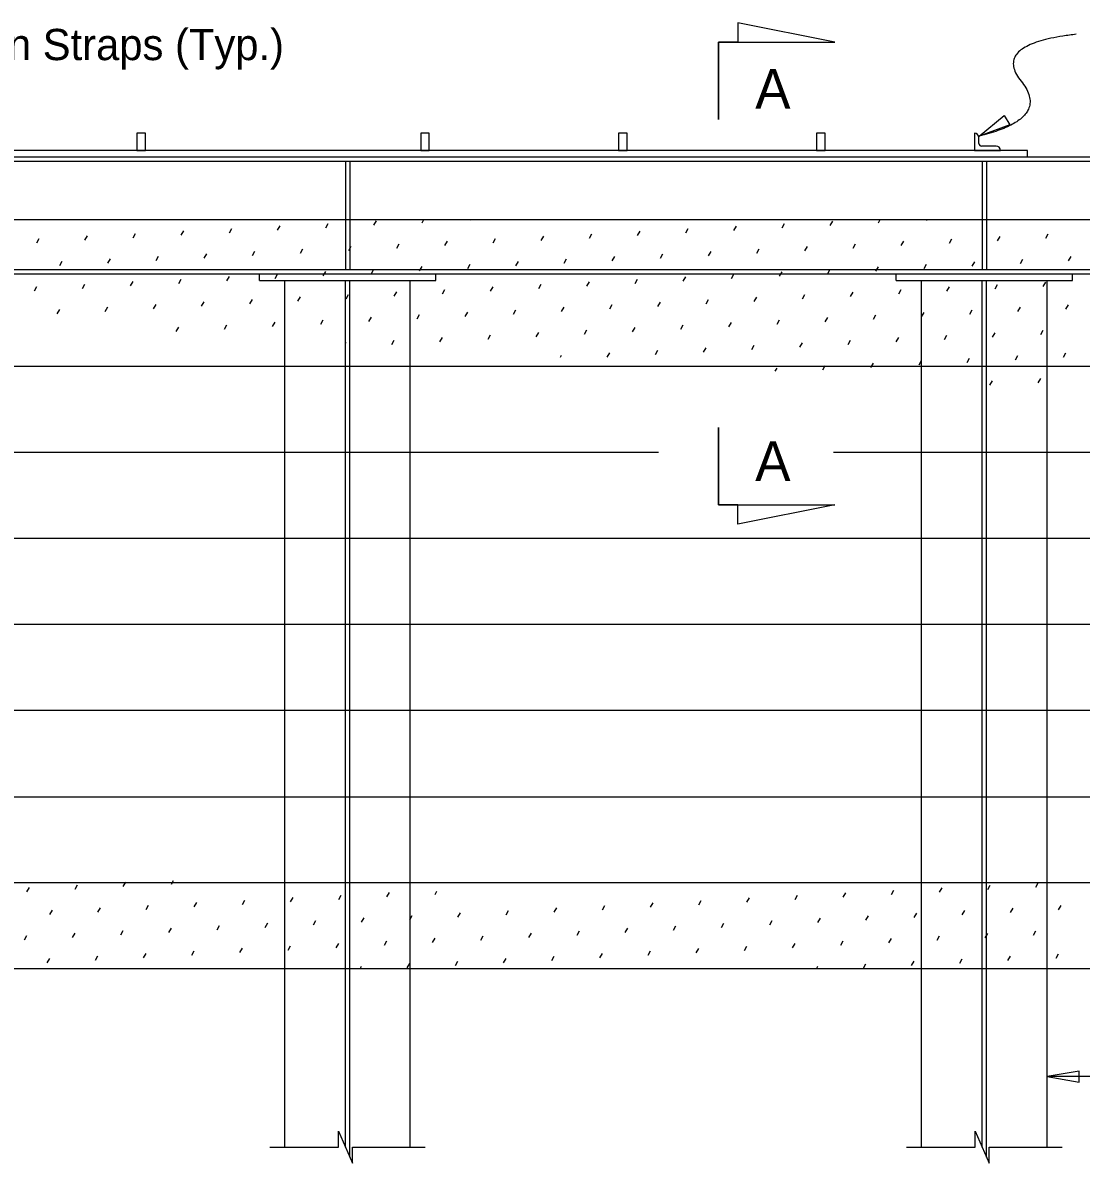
# Model space of a CAD drawing. Extents: x 10624 to 10731, y 76457 to 76509.
# Drawn here: x 10653.36 to 10663.61, y 76483.76 to 76494.8 of the extents above; entities that cross this region are included whole.
import ezdxf

# ---------------------------------------------------------------- set-up
doc = ezdxf.new("R2010")
doc.units = 0
for name, color, linetype in [('Dimension', 7, 'Continuous'), ('GroundLines', 7, 'Continuous'), ('SteelMisc', 7, 'Continuous'), ('SteelMisc_h', 7, 'Continuous'), ('Symbols', 7, 'Continuous'), ('TextStructures', 7, 'Continuous'), ('Wood', 7, 'Continuous'), ('Wood_h', 7, 'Continuous')]:
    doc.layers.add(name, color=color, linetype=linetype)

msp = doc.modelspace()

# ---------------------------------------------------------------- linework, layer by layer
at = {"layer": 'Dimension'}
for p, q in [((10655.831, 76492.793), (10655.855, 76492.835)), ((10656.298, 76492.818), (10656.322, 76492.86)), ((10656.764, 76492.842), (10656.788, 76492.884)), ((10657.23, 76492.866), (10657.248, 76492.897)), ((10657.697, 76492.891), (10657.701, 76492.897)), ((10660.25, 76492.792), (10660.274, 76492.834)), ((10660.717, 76492.816), (10660.741, 76492.858)), ((10661.183, 76492.84), (10661.207, 76492.882)), ((10661.649, 76492.865), (10661.668, 76492.897)), ((10662.116, 76492.889), (10662.121, 76492.897)), ((10653.499, 76492.672), (10653.523, 76492.714)), ((10653.965, 76492.696), (10653.99, 76492.738)), ((10654.432, 76492.72), (10654.456, 76492.762)), ((10654.898, 76492.745), (10654.922, 76492.787)), ((10655.365, 76492.769), (10655.389, 76492.811)), ((10657.918, 76492.67), (10657.942, 76492.712)), ((10658.384, 76492.694), (10658.409, 76492.736)), ((10658.851, 76492.718), (10658.875, 76492.76)), ((10659.317, 76492.743), (10659.341, 76492.785)), ((10659.784, 76492.767), (10659.808, 76492.809)), ((10662.337, 76492.668), (10662.361, 76492.71)), ((10662.803, 76492.692), (10662.828, 76492.734)), ((10663.27, 76492.717), (10663.294, 76492.759)), ((10656.052, 76492.572), (10656.076, 76492.614)), ((10656.519, 76492.597), (10656.543, 76492.639)), ((10656.985, 76492.621), (10657.009, 76492.663)), ((10657.451, 76492.645), (10657.476, 76492.687)), ((10660.471, 76492.571), (10660.495, 76492.613)), ((10660.938, 76492.595), (10660.962, 76492.637)), ((10661.404, 76492.619), (10661.428, 76492.661)), ((10661.87, 76492.644), (10661.895, 76492.686)), ((10653.72, 76492.451), (10653.744, 76492.493)), ((10654.186, 76492.475), (10654.211, 76492.517)), ((10654.653, 76492.499), (10654.677, 76492.541)), ((10655.119, 76492.524), (10655.144, 76492.566)), ((10655.586, 76492.548), (10655.61, 76492.59)), ((10658.139, 76492.449), (10658.163, 76492.491)), ((10658.605, 76492.473), (10658.63, 76492.515)), ((10659.072, 76492.497), (10659.096, 76492.539)), ((10659.538, 76492.522), (10659.563, 76492.564)), ((10660.005, 76492.546), (10660.029, 76492.588)), ((10662.558, 76492.447), (10662.582, 76492.489)), ((10663.024, 76492.471), (10663.049, 76492.513)), ((10663.491, 76492.496), (10663.515, 76492.538)), ((10656.273, 76492.351), (10656.297, 76492.393)), ((10656.74, 76492.376), (10656.764, 76492.418)), ((10657.206, 76492.4), (10657.23, 76492.442)), ((10657.672, 76492.424), (10657.697, 76492.466)), ((10660.692, 76492.349), (10660.716, 76492.391)), ((10661.159, 76492.374), (10661.183, 76492.416)), ((10661.625, 76492.398), (10661.649, 76492.44)), ((10662.091, 76492.423), (10662.116, 76492.465)), ((10653.941, 76492.229), (10653.965, 76492.271)), ((10654.407, 76492.254), (10654.432, 76492.296)), ((10654.874, 76492.278), (10654.898, 76492.32)), ((10655.34, 76492.303), (10655.365, 76492.345)), ((10655.807, 76492.327), (10655.831, 76492.369)), ((10658.36, 76492.228), (10658.384, 76492.27)), ((10658.826, 76492.252), (10658.851, 76492.294)), ((10659.293, 76492.276), (10659.317, 76492.318)), ((10659.759, 76492.301), (10659.784, 76492.343)), ((10660.226, 76492.325), (10660.25, 76492.367)), ((10662.779, 76492.226), (10662.803, 76492.268)), ((10663.245, 76492.25), (10663.27, 76492.292)), ((10653.475, 76492.205), (10653.499, 76492.247)), ((10656.494, 76492.13), (10656.518, 76492.172)), ((10656.961, 76492.155), (10656.985, 76492.197)), ((10657.427, 76492.179), (10657.451, 76492.221)), ((10657.894, 76492.203), (10657.918, 76492.245)), ((10660.913, 76492.128), (10660.937, 76492.17)), ((10661.38, 76492.153), (10661.404, 76492.195)), ((10661.846, 76492.177), (10661.87, 76492.219)), ((10662.313, 76492.202), (10662.337, 76492.244)), ((10654.162, 76492.008), (10654.186, 76492.05)), ((10654.628, 76492.033), (10654.653, 76492.075)), ((10655.095, 76492.057), (10655.119, 76492.099)), ((10655.561, 76492.082), (10655.586, 76492.124)), ((10656.028, 76492.106), (10656.052, 76492.148)), ((10658.581, 76492.007), (10658.605, 76492.049)), ((10659.047, 76492.031), (10659.072, 76492.073)), ((10659.514, 76492.055), (10659.538, 76492.097)), ((10659.98, 76492.08), (10660.005, 76492.122)), ((10660.447, 76492.104), (10660.471, 76492.146)), ((10663, 76492.005), (10663.024, 76492.047)), ((10663.466, 76492.029), (10663.491, 76492.071)), ((10653.696, 76491.984), (10653.72, 76492.026)), ((10656.715, 76491.909), (10656.74, 76491.951)), ((10657.182, 76491.934), (10657.206, 76491.976)), ((10657.648, 76491.958), (10657.672, 76492)), ((10658.115, 76491.982), (10658.139, 76492.024)), ((10661.134, 76491.907), (10661.159, 76491.949)), ((10661.601, 76491.932), (10661.625, 76491.974)), ((10662.067, 76491.956), (10662.091, 76491.998)), ((10662.534, 76491.98), (10662.558, 76492.022)), ((10654.849, 76491.812), (10654.874, 76491.854)), ((10655.316, 76491.836), (10655.34, 76491.878)), ((10655.782, 76491.86), (10655.807, 76491.902)), ((10656.249, 76491.885), (10656.273, 76491.927)), ((10658.802, 76491.786), (10658.826, 76491.828)), ((10659.268, 76491.81), (10659.293, 76491.852)), ((10659.735, 76491.834), (10659.759, 76491.876)), ((10660.201, 76491.859), (10660.226, 76491.901)), ((10660.668, 76491.883), (10660.692, 76491.925)), ((10663.221, 76491.784), (10663.245, 76491.826)), ((10656.936, 76491.688), (10656.961, 76491.73)), ((10657.403, 76491.713), (10657.427, 76491.755)), ((10657.869, 76491.737), (10657.893, 76491.779)), ((10658.336, 76491.761), (10658.36, 76491.803)), ((10661.355, 76491.686), (10661.38, 76491.728)), ((10661.822, 76491.711), (10661.846, 76491.753)), ((10662.288, 76491.735), (10662.312, 76491.777)), ((10662.755, 76491.759), (10662.779, 76491.801)), ((10656.492, 76491.702), (10656.494, 76491.706)), ((10659.023, 76491.565), (10659.047, 76491.607)), ((10659.49, 76491.589), (10659.514, 76491.631)), ((10659.956, 76491.613), (10659.98, 76491.655)), ((10660.422, 76491.638), (10660.447, 76491.68)), ((10660.889, 76491.662), (10660.913, 76491.704)), ((10663.442, 76491.563), (10663.466, 76491.605)), ((10658.571, 76491.564), (10658.581, 76491.582)), ((10661.576, 76491.465), (10661.601, 76491.507)), ((10662.043, 76491.49), (10662.067, 76491.532)), ((10662.509, 76491.514), (10662.533, 76491.556)), ((10662.976, 76491.538), (10663, 76491.58)), ((10660.649, 76491.427), (10660.668, 76491.459)), ((10661.11, 76491.441), (10661.134, 76491.483)), ((10662.73, 76491.293), (10662.755, 76491.335)), ((10663.197, 76491.317), (10663.221, 76491.359)), ((10653.403, 76486.387), (10653.428, 76486.429)), ((10653.87, 76486.411), (10653.894, 76486.453)), ((10654.336, 76486.436), (10654.36, 76486.478)), ((10654.803, 76486.46), (10654.823, 76486.496)), ((10662.241, 76486.383), (10662.266, 76486.425)), ((10662.708, 76486.408), (10662.732, 76486.45)), ((10663.174, 76486.432), (10663.198, 76486.474)), ((10655.49, 76486.263), (10655.514, 76486.305)), ((10655.956, 76486.288), (10655.981, 76486.33)), ((10656.423, 76486.312), (10656.447, 76486.354)), ((10656.889, 76486.336), (10656.914, 76486.378)), ((10657.356, 76486.361), (10657.373, 76486.391)), ((10659.909, 76486.261), (10659.933, 76486.303)), ((10660.375, 76486.286), (10660.4, 76486.328)), ((10660.842, 76486.31), (10660.866, 76486.352)), ((10661.308, 76486.334), (10661.333, 76486.376)), ((10661.775, 76486.359), (10661.799, 76486.401)), ((10653.624, 76486.166), (10653.649, 76486.208)), ((10654.091, 76486.19), (10654.115, 76486.232)), ((10654.557, 76486.214), (10654.581, 76486.256)), ((10655.024, 76486.239), (10655.048, 76486.281)), ((10658.043, 76486.164), (10658.068, 76486.206)), ((10658.51, 76486.188), (10658.534, 76486.23)), ((10658.976, 76486.213), (10659, 76486.255)), ((10659.443, 76486.237), (10659.467, 76486.279)), ((10662.462, 76486.162), (10662.487, 76486.204)), ((10662.929, 76486.187), (10662.953, 76486.229)), ((10663.395, 76486.211), (10663.419, 76486.253)), ((10655.711, 76486.042), (10655.735, 76486.084)), ((10656.178, 76486.067), (10656.202, 76486.109)), ((10656.644, 76486.091), (10656.668, 76486.133)), ((10657.11, 76486.115), (10657.135, 76486.157)), ((10657.577, 76486.14), (10657.601, 76486.182)), ((10660.13, 76486.04), (10660.154, 76486.082)), ((10660.597, 76486.065), (10660.621, 76486.107)), ((10661.063, 76486.089), (10661.087, 76486.131)), ((10661.529, 76486.113), (10661.554, 76486.155)), ((10661.996, 76486.138), (10662.02, 76486.18)), ((10653.845, 76485.945), (10653.87, 76485.987)), ((10654.312, 76485.969), (10654.336, 76486.011)), ((10654.778, 76485.993), (10654.803, 76486.035)), ((10655.245, 76486.018), (10655.269, 76486.06)), ((10658.264, 76485.943), (10658.289, 76485.985)), ((10658.731, 76485.967), (10658.755, 76486.009)), ((10659.197, 76485.992), (10659.222, 76486.034)), ((10659.664, 76486.016), (10659.688, 76486.058)), ((10662.683, 76485.941), (10662.708, 76485.983)), ((10663.15, 76485.965), (10663.174, 76486.007)), ((10653.379, 76485.92), (10653.403, 76485.962)), ((10655.932, 76485.821), (10655.956, 76485.863)), ((10656.399, 76485.845), (10656.423, 76485.887)), ((10656.865, 76485.87), (10656.889, 76485.912)), ((10657.331, 76485.894), (10657.356, 76485.936)), ((10657.798, 76485.919), (10657.822, 76485.961)), ((10660.351, 76485.819), (10660.375, 76485.861)), ((10660.818, 76485.844), (10660.842, 76485.886)), ((10661.284, 76485.868), (10661.308, 76485.91)), ((10661.75, 76485.892), (10661.775, 76485.934)), ((10662.217, 76485.917), (10662.241, 76485.959)), ((10654.066, 76485.724), (10654.091, 76485.766)), ((10654.533, 76485.748), (10654.557, 76485.79)), ((10654.999, 76485.772), (10655.024, 76485.814)), ((10655.466, 76485.797), (10655.49, 76485.839)), ((10658.485, 76485.722), (10658.51, 76485.764)), ((10658.952, 76485.746), (10658.976, 76485.788)), ((10659.418, 76485.771), (10659.443, 76485.813)), ((10659.885, 76485.795), (10659.909, 76485.837)), ((10662.904, 76485.72), (10662.929, 76485.762)), ((10663.371, 76485.744), (10663.395, 76485.786)), ((10653.6, 76485.699), (10653.624, 76485.741)), ((10656.177, 76485.641), (10656.177, 76485.642)), ((10656.629, 76485.641), (10656.644, 76485.666)), ((10657.086, 76485.649), (10657.11, 76485.691)), ((10657.552, 76485.673), (10657.577, 76485.715)), ((10658.019, 76485.698), (10658.043, 76485.74)), ((10661.049, 76485.641), (10661.063, 76485.665)), ((10661.505, 76485.647), (10661.529, 76485.689)), ((10661.971, 76485.671), (10661.996, 76485.713)), ((10662.438, 76485.696), (10662.462, 76485.738)), ((10670.147, 76484.596), (10663.283, 76484.596))]:
    msp.add_line(p, q, dxfattribs=at)
for points in [[(10662.624, 76493.705), (10662.869, 76493.906), (10662.921, 76493.815)], [(10663.283, 76484.596), (10663.595, 76484.543), (10663.595, 76484.649)]]:
    msp.add_lwpolyline(points, close=True, dxfattribs=at)
msp.add_open_spline([(10663.566, 76494.691), (10662.74, 76494.598), (10663.324, 76493.874), (10662.624, 76493.705)], degree=2, dxfattribs=at)
at = {"layer": 'GroundLines'}
msp.add_line((10629.323, 76487.307), (10670.364, 76487.307), dxfattribs=at)
at = {"layer": 'SteelMisc'}
for p, q in [((10662.581, 76493.733), (10662.581, 76493.567)), ((10662.623, 76493.634), (10662.623, 76493.692)), ((10662.79, 76493.608), (10662.649, 76493.608)), ((10631.234, 76493.504), (10669.45, 76493.504)), ((10662.581, 76493.567), (10662.831, 76493.567)), ((10631.234, 76493.462), (10669.45, 76493.462)), ((10656.491, 76492.406), (10656.491, 76493.462)), ((10656.532, 76492.406), (10656.532, 76493.462)), ((10662.657, 76492.406), (10662.657, 76493.462)), ((10662.699, 76492.406), (10662.699, 76493.462)), ((10631.234, 76492.412), (10669.45, 76492.412)), ((10630.987, 76492.37), (10669.696, 76492.37)), ((10655.654, 76492.307), (10655.654, 76492.37)), ((10655.654, 76492.307), (10657.363, 76492.307)), ((10655.901, 76487.307), (10655.901, 76492.307)), ((10657.116, 76487.307), (10657.116, 76492.307)), ((10657.363, 76492.307), (10657.363, 76492.37)), ((10661.821, 76492.307), (10661.821, 76492.37)), ((10661.821, 76492.307), (10663.529, 76492.307)), ((10662.067, 76487.307), (10662.067, 76492.307)), ((10663.283, 76487.307), (10663.283, 76492.307)), ((10663.529, 76492.307), (10663.529, 76492.37))]:
    msp.add_line(p, q, dxfattribs=at)
for points in [[(10654.467, 76493.567), (10654.55, 76493.567), (10654.55, 76493.733), (10654.467, 76493.733)], [(10657.217, 76493.567), (10657.3, 76493.567), (10657.3, 76493.733), (10657.217, 76493.733)], [(10659.133, 76493.567), (10659.217, 76493.567), (10659.217, 76493.733), (10659.133, 76493.733)], [(10661.05, 76493.567), (10661.133, 76493.567), (10661.133, 76493.733), (10661.05, 76493.733)], [(10637.592, 76493.504), (10663.092, 76493.504), (10663.092, 76493.567), (10637.592, 76493.567)]]:
    msp.add_lwpolyline(points, close=True, dxfattribs=at)
for centre, radius, start, end in [((10662.581, 76493.692), 0.0417, 0, 90), ((10662.649, 76493.634), 0.026, 180, 270), ((10662.79, 76493.567), 0.0417, 0, 90)]:
    msp.add_arc(centre, radius, start, end, dxfattribs=at)
at = {"layer": 'SteelMisc_h'}
for p, q in [((10656.487, 76483.913), (10656.487, 76492.307)), ((10656.529, 76483.816), (10656.529, 76492.307)), ((10662.654, 76483.913), (10662.654, 76492.307)), ((10662.696, 76483.816), (10662.696, 76492.307)), ((10655.901, 76483.913), (10655.901, 76487.307)), ((10657.116, 76483.913), (10657.116, 76487.307)), ((10662.067, 76483.913), (10662.067, 76487.307)), ((10663.283, 76483.913), (10663.283, 76487.307))]:
    msp.add_line(p, q, dxfattribs=at)
at = {"layer": 'Symbols'}
for points in [[(10660.101, 76493.865), (10660.101, 76494.615), (10661.226, 76494.615), (10660.289, 76494.802), (10660.289, 76494.615), (10660.101, 76494.615)], [(10660.101, 76490.884), (10660.101, 76490.134), (10661.226, 76490.134), (10660.289, 76489.946), (10660.289, 76490.134), (10660.101, 76490.134)]]:
    msp.add_lwpolyline(points, close=True, dxfattribs=at)
for points in [[(10655.755, 76483.913), (10656.42, 76483.913), (10656.42, 76484.068), (10656.555, 76483.758), (10656.555, 76483.913), (10657.261, 76483.913)], [(10661.921, 76483.913), (10662.587, 76483.913), (10662.587, 76484.068), (10662.722, 76483.758), (10662.722, 76483.913), (10663.428, 76483.913)]]:
    msp.add_lwpolyline(points, dxfattribs=at)
at = {"layer": 'TextStructures'}
msp.add_line((10631.234, 76492.897), (10669.486, 76492.897), dxfattribs=at)
at = {"layer": 'Wood'}
for p, q in [((10655.901, 76491.474), (10650.949, 76491.474)), ((10662.067, 76491.474), (10657.116, 76491.474)), ((10668.234, 76491.474), (10663.283, 76491.474)), ((10655.901, 76490.641), (10650.949, 76490.641)), ((10659.52, 76490.641), (10657.116, 76490.641)), ((10662.067, 76490.641), (10661.216, 76490.641)), ((10668.234, 76490.641), (10663.283, 76490.641)), ((10655.901, 76489.807), (10650.949, 76489.807)), ((10662.067, 76489.807), (10657.116, 76489.807)), ((10668.234, 76489.807), (10663.283, 76489.807)), ((10655.901, 76488.974), (10650.949, 76488.974)), ((10662.067, 76488.974), (10657.116, 76488.974)), ((10668.234, 76488.974), (10663.283, 76488.974)), ((10655.901, 76488.141), (10650.949, 76488.141)), ((10662.067, 76488.141), (10657.116, 76488.141)), ((10668.234, 76488.141), (10663.283, 76488.141))]:
    msp.add_line(p, q, dxfattribs=at)
at = {"layer": 'Wood_h'}
for p, q in [((10657.116, 76491.474), (10655.901, 76491.474)), ((10663.283, 76491.474), (10662.067, 76491.474)), ((10657.116, 76490.641), (10655.901, 76490.641)), ((10663.283, 76490.641), (10662.067, 76490.641)), ((10657.116, 76489.807), (10655.901, 76489.807)), ((10663.283, 76489.807), (10662.067, 76489.807)), ((10657.116, 76488.974), (10655.901, 76488.974)), ((10663.283, 76488.974), (10662.067, 76488.974)), ((10657.116, 76488.141), (10655.901, 76488.141)), ((10663.283, 76488.141), (10662.067, 76488.141)), ((10669.45, 76486.474), (10631.234, 76486.474)), ((10669.45, 76485.641), (10631.234, 76485.641))]:
    msp.add_line(p, q, dxfattribs=at)

# ---------------------------------------------------------------- texts
at = {"layer": 'Dimension'}
msp.add_text('Deck Hold Down Straps (Typ.)', height=0.3024, dxfattribs=at).set_placement((10650.432, 76494.441))
at = {"layer": 'TextStructures'}
for p in [(10660.456, 76493.97), (10660.456, 76490.365)]:
    msp.add_text('A', height=0.384, dxfattribs=at).set_placement(p)

doc.saveas('drawing.dxf')
